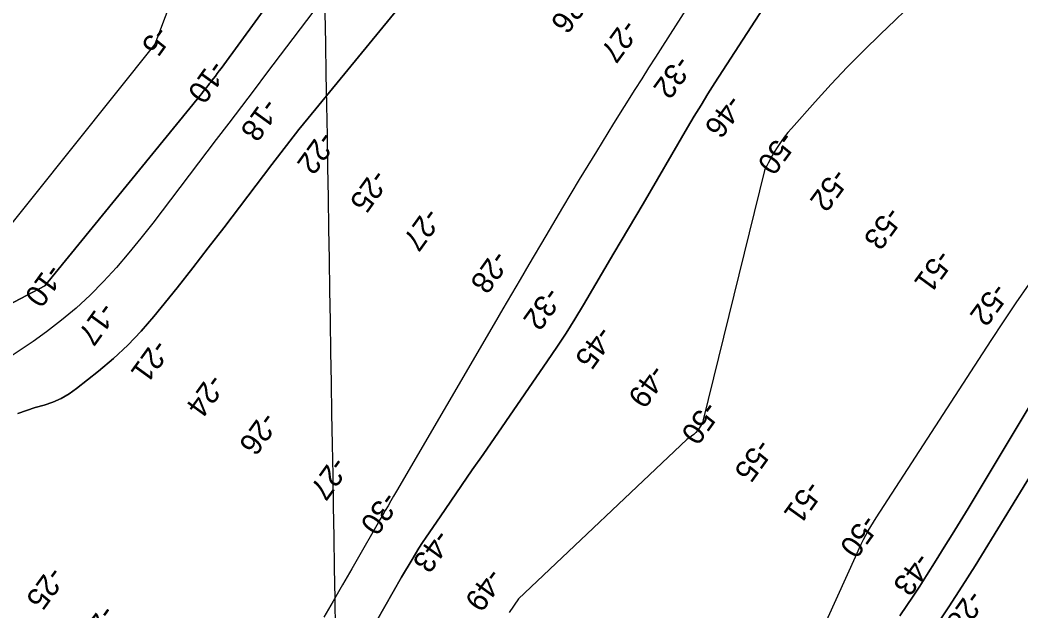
# Model space of a CAD drawing. Extents: x 3879599 to 3900814, y 146526 to 168888.
# Drawn here: x 3893542 to 3895080, y 159864 to 160771 of the extents above; entities that cross this region are included whole.
import ezdxf

# ---------------------------------------------------------------- set-up
doc = ezdxf.new("R2010")
doc.units = 0
for name, color, linetype in [('V-GRID-MAJR', 7, 'Continuous'), ('V-RIVR-RANG', 7, 'Continuous'), ('V-TOPO-DPTH', 7, 'Continuous'), ('V-TOPO-MAJR', 7, 'Continuous'), ('V-TOPO-MINR', 7, 'Continuous')]:
    doc.layers.add(name, color=color, linetype=linetype)

msp = doc.modelspace()

# ---------------------------------------------------------------- linework, layer by layer
at = {"layer": 'V-GRID-MAJR'}
msp.add_spline([(3894134.7, 153416.7), (3894080.4, 156663.6), (3893979, 162723.9), (3893946.7, 164659.1)], degree=3, dxfattribs=at)
at = {"layer": 'V-TOPO-DPTH'}
for points in [[(3893486.9, 160314.4), (3893580.4, 160363.2), (3893819.2, 160655.3), (3893821.7, 160658.4), (3893824.1, 160661.4), (3893826.5, 160664.5), (3893829, 160667.6), (3893831.5, 160670.8), (3893833.8, 160673.8), (3893834.9, 160675.2), (3893836.1, 160676.7), (3893839.7, 160681.5), (3893842.6, 160685.3), (3893845.5, 160689.2), (3893848.4, 160693.1), (3893851.3, 160697), (3894064.7, 160989.4), (3894069.6, 160996.4), (3894074.2, 161003.4), (3894078.6, 161010.6), (3894082.8, 161017.9), (3894102.6, 161054.3), (3894109.9, 161069.4), (3894278.8, 161104.1)], [(3894617.8, 160869.1), (3894529.4, 160731.2), (3894518.8, 160714.5), (3894508.2, 160697.9), (3894497.6, 160681.1), (3894487.1, 160664.4), (3894454.5, 160612.4), (3894428, 160569.6), (3894401.7, 160526.6), (3894375.7, 160483.3), (3894350.1, 160439.9), (3894324.3, 160396), (3894311, 160373.2), (3894297.7, 160350.5), (3894284.4, 160327.8), (3894271.1, 160305.1), (3894120.8, 160048.1), (3894116.5, 160040.7), (3894112.2, 160033.3), (3894107.9, 160025.8), (3894103.5, 160018.4), (3894099.3, 160011), (3894095, 160003.6), (3894090.7, 159996.1), (3894086.4, 159988.7), (3894066.5, 159953.8), (3894052.3, 159929), (3894037.9, 159904.2), (3894023.5, 159879.5), (3894009, 159854.8)], [(3894617.8, 160869.1), (3894529.4, 160731.2), (3894518.8, 160714.5), (3894508.2, 160697.9), (3894497.6, 160681.1), (3894487.1, 160664.4), (3894454.5, 160612.4), (3894428, 160569.6), (3894401.7, 160526.6), (3894375.7, 160483.3), (3894350.1, 160439.9), (3894324.3, 160396), (3894311, 160373.2), (3894297.7, 160350.5), (3894284.4, 160327.8), (3894271.1, 160305.1), (3894120.8, 160048.1), (3894116.5, 160040.7), (3894112.2, 160033.3), (3894107.9, 160025.8), (3894103.5, 160018.4), (3894099.3, 160011), (3894095, 160003.6), (3894090.7, 159996.1), (3894086.4, 159988.7), (3894066.5, 159953.8), (3894052.3, 159929), (3894037.9, 159904.2), (3894023.5, 159879.5), (3894009, 159854.8)], [(3894156.4, 160829.6), (3893985.2, 160620.7), (3893971, 160603.1), (3893956.9, 160585.5), (3893943, 160567.6), (3893929.2, 160549.7), (3893855.4, 160452.3), (3893831.7, 160421.4), (3893807.9, 160390.8), (3893783.7, 160360.3), (3893759.3, 160330.1), (3893748, 160316.2), (3893728.4, 160293.7), (3893707.9, 160272.1), (3893686.1, 160251.8), (3893663.3, 160232.5), (3893629.4, 160205.5), (3893617.8, 160197.4), (3893605.7, 160190.4), (3893592.9, 160184.9), (3893579.5, 160180.4), (3893565.9, 160176.5), (3893552.3, 160172.2), (3893538.9, 160167.4)], [(3893538.9, 160167.4), (3893552.3, 160172.2), (3893565.9, 160176.5), (3893579.5, 160180.4), (3893592.9, 160184.9), (3893605.7, 160190.4), (3893617.8, 160197.4), (3893629.4, 160205.5), (3893663.3, 160232.5), (3893686.1, 160251.8), (3893707.9, 160272.1), (3893728.4, 160293.7), (3893748, 160316.2), (3893759.3, 160330.1), (3893783.7, 160360.3), (3893807.9, 160390.8), (3893831.7, 160421.4), (3893855.4, 160452.3), (3893929.2, 160549.7), (3893943, 160567.6), (3893956.9, 160585.5), (3893971, 160603.1), (3893985.2, 160620.7), (3894156.4, 160829.6)], [(3894089.9, 159848.4), (3894102.8, 159871), (3894115.8, 159893.5), (3894128.8, 159916), (3894144.7, 159943.2), (3894150, 159951.9), (3894155.3, 159960.6), (3894160.9, 159969.2), (3894166.6, 159977.7), (3894187.9, 160008.8), (3894204.3, 160032.8), (3894220.8, 160056.7), (3894237.3, 160080.7), (3894253.8, 160104.6), (3894353.1, 160248.1), (3894367.4, 160269.3), (3894381.4, 160290.7), (3894395, 160312.4), (3894408.2, 160334.2), (3894455, 160413.2), (3894477.3, 160451.1), (3894499.7, 160489), (3894521.9, 160527), (3894544.1, 160565), (3894568, 160606.2), (3894578.3, 160623.5), (3894588.7, 160640.8), (3894599.3, 160657.9), (3894610.1, 160674.9), (3894702.4, 160818.2)], [(3894089.9, 159848.4), (3894102.8, 159871), (3894115.8, 159893.5), (3894128.8, 159916), (3894144.7, 159943.2), (3894150, 159951.9), (3894155.3, 159960.6), (3894160.9, 159969.2), (3894166.6, 159977.7), (3894187.9, 160008.8), (3894204.3, 160032.8), (3894220.8, 160056.7), (3894237.3, 160080.7), (3894253.8, 160104.6), (3894353.1, 160248.1), (3894367.4, 160269.3), (3894381.4, 160290.7), (3894395, 160312.4), (3894408.2, 160334.2), (3894455, 160413.2), (3894477.3, 160451.1), (3894499.7, 160489), (3894521.9, 160527), (3894544.1, 160565), (3894568, 160606.2), (3894578.3, 160623.5), (3894588.7, 160640.8), (3894599.3, 160657.9), (3894610.1, 160674.9), (3894702.4, 160818.2)], [(3894948.8, 159839.8), (3894969.6, 159870.8), (3894989.9, 159902.2), (3895009.8, 159933.8), (3895143.7, 160151.3), (3895150.3, 160162), (3895156.8, 160172.8), (3895163.3, 160183.6), (3895169.7, 160194.3), (3895176.7, 160206.2), (3895179.7, 160211.1), (3895182.7, 160215.9), (3895185.7, 160220.7), (3895188.8, 160225.5), (3895201.4, 160244.5), (3895210.9, 160258.7), (3895220.4, 160272.9), (3895230.1, 160287), (3895239.9, 160301.1), (3895370.4, 160487.8), (3895373.5, 160492.3), (3895462.4, 160435.8), (3895459.6, 160430.9)], [(3894894.4, 159856.8), (3894914.6, 159886.8), (3894919.9, 159894.7), (3894925.1, 159902.6), (3894930.2, 159910.6), (3894935.3, 159918.6), (3894950.1, 159942.2), (3894962.4, 159962), (3894974.7, 159981.9), (3894986.9, 160001.8), (3894999, 160021.8), (3895100.7, 160190.5)], [(3895100.7, 160190.5), (3894999, 160021.8), (3894986.9, 160001.8), (3894974.7, 159981.9), (3894962.4, 159962), (3894950.1, 159942.2), (3894935.3, 159918.6), (3894930.2, 159910.6), (3894925.1, 159902.6), (3894919.9, 159894.7), (3894914.6, 159886.8), (3894894.4, 159856.8)], [(3895143.7, 160151.3), (3895009.8, 159933.8), (3894989.9, 159902.2), (3894969.6, 159870.8), (3894948.8, 159839.8)]]:
    msp.add_lwpolyline(points, dxfattribs=at)
at = {"layer": 'V-TOPO-MAJR'}
for points in [[(3894901.9, 160785.2), (3894886.8, 160770.9), (3894864.5, 160749.6), (3894838.7, 160724.4), (3894813.3, 160698.8), (3894788.5, 160672.6), (3894764.2, 160645.9), (3894727.6, 160605), (3894722, 160598.4), (3894716.7, 160591.6), (3894711.7, 160584.6), (3894706.9, 160577.4), (3894700.1, 160566.7), (3894698.9, 160564.7), (3894696.7, 160560.7), (3894695.6, 160558.7), (3894693.8, 160555.3), (3894691.8, 160551.5), (3894689.9, 160547.7), (3894688, 160543.9), (3894686.1, 160540.1), (3894592.2, 160157.8), (3894590.9, 160153.5), (3894589.9, 160151.5), (3894588.8, 160149.5), (3894587, 160146.5), (3894584.7, 160143.2), (3894583.3, 160141.5), (3894580.5, 160138.3), (3894577.5, 160135.4), (3894573.9, 160132.4), (3894571.6, 160130.6), (3894569.2, 160128.9), (3894566.7, 160127.3), (3894308.1, 159882.7), (3894294, 159862)], [(3894687.4, 159641.4), (3894828.5, 159953.1), (3894831.7, 159960.1), (3894835, 159967), (3894838.5, 159973.9), (3894842, 159980.7), (3894845.7, 159987.5), (3894849.5, 159994.2), (3894853.5, 160000.8), (3894857.6, 160007.3), (3895015.3, 160250.1), (3895034.4, 160279.2), (3895053.6, 160308.2), (3895073, 160337.1), (3895092.6, 160365.9)]]:
    msp.add_lwpolyline(points, dxfattribs=at)
at = {"layer": 'V-TOPO-MINR'}
for points in [[(3893899.6, 161131.1), (3893749.5, 160734.2), (3893499.2, 160421.6)], [(3894109.9, 161069.4), (3894102.6, 161054.3), (3894082.8, 161017.9), (3894078.6, 161010.6), (3894074.2, 161003.4), (3894069.6, 160996.4), (3894064.7, 160989.4), (3893851.3, 160697), (3893848.4, 160693.1), (3893845.5, 160689.2), (3893842.6, 160685.3), (3893839.7, 160681.5), (3893836.1, 160676.7), (3893834.9, 160675.2), (3893833.8, 160673.8), (3893831.5, 160670.8), (3893829, 160667.6), (3893826.5, 160664.5), (3893824.1, 160661.4), (3893821.7, 160658.4), (3893819.2, 160655.3), (3893580.4, 160363.2), (3893486.9, 160314.4)], [(3894617.8, 160869.1), (3894529.4, 160731.2), (3894518.8, 160714.5), (3894508.2, 160697.9), (3894497.6, 160681.1), (3894487.1, 160664.4), (3894454.5, 160612.4), (3894428, 160569.6), (3894401.7, 160526.6), (3894375.7, 160483.3), (3894350.1, 160439.9), (3894324.3, 160396), (3894311, 160373.2), (3894297.7, 160350.5), (3894284.4, 160327.8), (3894271.1, 160305.1), (3894120.8, 160048.1), (3894116.5, 160040.7), (3894112.2, 160033.3), (3894107.9, 160025.8), (3894103.5, 160018.4), (3894099.3, 160011), (3894095, 160003.6), (3894090.7, 159996.1), (3894086.4, 159988.7), (3894066.5, 159953.8), (3894052.3, 159929), (3894037.9, 159904.2), (3894023.5, 159879.5), (3894009, 159854.8)], [(3894053.7, 160864.5), (3893921.4, 160689.7), (3893902.1, 160664.2), (3893882.7, 160638.7), (3893863.4, 160613.2), (3893844, 160587.7), (3893746.5, 160459.7), (3893728.3, 160436.6), (3893709.8, 160413.9), (3893690.5, 160391.7), (3893670.8, 160370), (3893650.1, 160349.1), (3893628.7, 160329.2), (3893606.2, 160310.5), (3893583, 160292.6), (3893562.7, 160278.1), (3893546, 160266.5), (3893528.9, 160255.4)], [(3894156.4, 160829.6), (3893985.2, 160620.7), (3893971, 160603.1), (3893956.9, 160585.5), (3893943, 160567.6), (3893929.2, 160549.7), (3893855.4, 160452.3), (3893831.7, 160421.4), (3893807.9, 160390.8), (3893783.7, 160360.3), (3893759.3, 160330.1), (3893748, 160316.2), (3893728.4, 160293.7), (3893707.9, 160272.1), (3893686.1, 160251.8), (3893663.3, 160232.5), (3893629.4, 160205.5), (3893617.8, 160197.4), (3893605.7, 160190.4), (3893592.9, 160184.9), (3893579.5, 160180.4), (3893565.9, 160176.5), (3893552.3, 160172.2), (3893538.9, 160167.4)], [(3894702.4, 160818.2), (3894610.1, 160674.9), (3894599.3, 160657.9), (3894588.7, 160640.8), (3894578.3, 160623.5), (3894568, 160606.2), (3894544.1, 160565), (3894521.9, 160527), (3894499.7, 160489), (3894477.3, 160451.1), (3894455, 160413.2), (3894408.2, 160334.2), (3894395, 160312.4), (3894381.4, 160290.7), (3894367.4, 160269.3), (3894353.1, 160248.1), (3894253.8, 160104.6), (3894237.3, 160080.7), (3894220.8, 160056.7), (3894204.3, 160032.8), (3894187.9, 160008.8), (3894166.6, 159977.7), (3894160.9, 159969.2), (3894155.3, 159960.6), (3894150, 159951.9), (3894144.7, 159943.2), (3894128.8, 159916), (3894115.8, 159893.5), (3894102.8, 159871), (3894089.9, 159848.4)], [(3894894.4, 159856.8), (3894914.6, 159886.8), (3894919.9, 159894.7), (3894925.1, 159902.6), (3894930.2, 159910.6), (3894935.3, 159918.6), (3894950.1, 159942.2), (3894962.4, 159962), (3894974.7, 159981.9), (3894986.9, 160001.8), (3894999, 160021.8), (3895100.7, 160190.5)], [(3894948.8, 159839.8), (3894969.6, 159870.8), (3894989.9, 159902.2), (3895009.8, 159933.8), (3895143.7, 160151.3)]]:
    msp.add_lwpolyline(points, dxfattribs=at)

# ---------------------------------------------------------------- texts
at = {"layer": 'V-RIVR-RANG'}
for s, rotation, p in [('-26', 233.6783, (3894394.6, 160819.7)), ('-27', 233.823, (3894469.9, 160774.8)), ('-5', 234.2083, (3893750.8, 160764.7)), ('-10', 234.2083, (3893836.3, 160712.3)), ('-32', 233.823, (3894551.9, 160719.3)), ('-18', 234.2083, (3893917.5, 160653.9)), ('-46', 233.823, (3894630.7, 160659.1)), ('-22', 234.2083, (3894004.3, 160603.3)), ('-50', 233.823, (3894711.9, 160602.8)), ('-25', 234.2083, (3894085.3, 160544.6)), ('-52', 233.823, (3894792.6, 160546.2)), ('-27', 234.2083, (3894166.1, 160485.7)), ('-53', 233.823, (3894875.2, 160487.4)), ('-28', 234.3533, (3894270.5, 160420.4)), ('-51', 233.823, (3894952.8, 160421.4)), ('-10', 234.1183, (3893586, 160399.5)), ('-52', 233.823, (3895038.2, 160370.5)), ('-32', 234.3533, (3894351.6, 160364.1)), ('-17', 234.1183, (3893666.9, 160340.8)), ('-45', 234.3533, (3894431.2, 160304.3)), ('-21', 234.1183, (3893749, 160283.5)), ('-49', 234.3533, (3894512.7, 160245)), ('-24', 234.1183, (3893834.1, 160230.7)), ('-50', 234.3533, (3894594.3, 160188.7)), ('-26', 234.1183, (3893915.4, 160172.4)), ('-55', 234.3533, (3894675.9, 160131)), ('-27', 234.2611, (3894023.4, 160103.4)), ('-51', 234.3533, (3894752.1, 160067)), ('-30', 234.2611, (3894101.4, 160049.9)), ('-50', 234.3533, (3894838, 160014.8)), ('-43', 234.2611, (3894181.9, 159991.8)), ('-43', 234.3533, (3894920, 159956.5)), ('-25', 233.9183, (3893588.3, 159935)), ('-49', 234.2611, (3894262.1, 159932.6)), ('-28', 234.3533, (3895000.8, 159899.1)), ('-27', 233.9183, (3893668.8, 159875.7))]:
    msp.add_text(s, height=33.5, rotation=rotation, dxfattribs=at).set_placement(p)

doc.saveas('drawing.dxf')
